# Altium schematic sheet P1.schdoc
size 297 x 209 mm; Symbol: Drawing-Symbol_A4; @Create Time: 13:52:45; @Update Time: 20:21:33; Border: 1; Width: 1170; Height: 825; Region Start: 1; X Region Count: 6; Y Region Count: 4; Blade Width: 10; Title Block Position: 3; Title Block: 1; @Board Name: ADC; Company: 嘉立创EDA; Version: V1.0; Page Size: A4; @Project Name: stm32f4; @Page Count: 1; @Update Date: 2025-11-17; @Create Date: 2025-11-02; @Schematic Name: Schematic2; @Page No: 1; @Page Name: P1; Device: Drawing-Symbol_A4
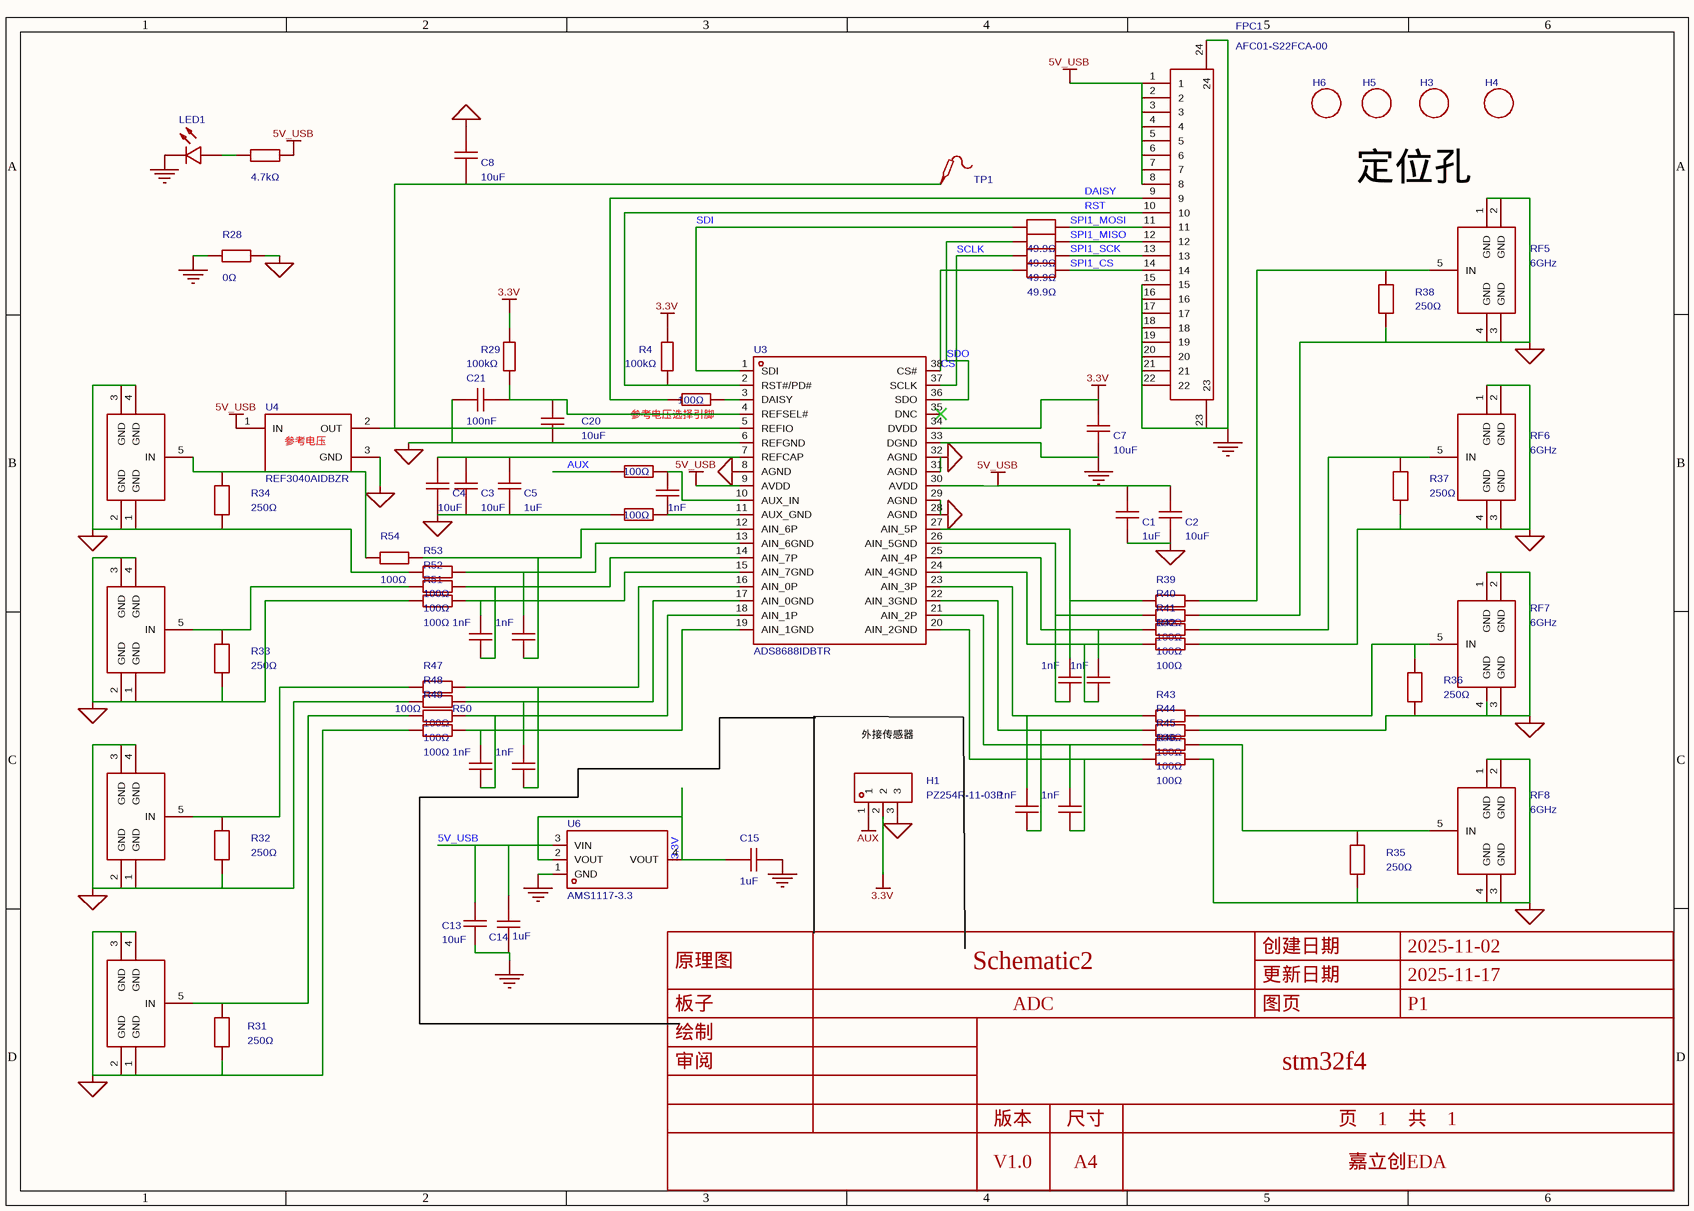
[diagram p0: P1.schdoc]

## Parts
C1  1uF  [C0603]
C2  10uF  [C0603]
C3  10uF  [C0603]
C4  10uF  [C0603]
C5  1uF  [C0603]
C6  1nF  [C0603]
C7  10uF  [C0603]
C8  10uF  [C0603]
C9  1nF  [C0603]
C10  1nF  [C0603]
C11  1nF  [C0603]
C12  1nF  [C0603]
C13  10uF  [C0603]
C14  1uF  [C0603]
C15  1uF  [C0603]
C16  1nF  [C0603]
C17  1nF  [C0603]
C18  1nF  [C0603]
C19  1nF  [C0603]
C20  10uF  [C0603]
C21  100nF  [C0402]
FPC1  AFC01-S22FCA-00  [FPC-SMD_P0.5-22P_FGS-XJ-H2.0]
H1  PZ254R-11-03P  [HDR-TH_3P-P2.54-H-M-W10.4]
H3  m3_3  [m3 125x300]  (value not drawn)
H4  m3_3  [m3 125x300]  (value not drawn)
H5  m3_3  [m3 125x300]  (value not drawn)
H6  m3_3  [m3 125x300]  (value not drawn)
LED1  19-217/R6C-AL1M2VY/3T  [LED0603-RD]  (value not drawn)
R1  100Ω  [R0603]
R3  100Ω  [R0603]
R4  100kΩ  [R0603]
R26  4.7kΩ  [R0402]
R28  0Ω  [R0603]
R29  100kΩ  [R0603]
R30  100Ω  [R0603]
R31  250Ω  [R1206]
R32  250Ω  [R1206]
R33  250Ω  [R1206]
R34  250Ω  [R1206]
R35  250Ω  [R1206]
R36  250Ω  [R1206]
R37  250Ω  [R1206]
R38  250Ω  [R1206]
R39  100Ω  [R0603]
R40  100Ω  [R0603]
R41  100Ω  [R0603]
R42  100Ω  [R0603]
R43  100Ω  [R0603]
R44  100Ω  [R0603]
R45  100Ω  [R0603]
R46  100Ω  [R0603]
R47  100Ω  [R0603]
R48  100Ω  [R0603]
R49  100Ω  [R0603]
R50  100Ω  [R0603]
R51  100Ω  [R0603]
R52  100Ω  [R0603]
R53  100Ω  [R0603]
R54  100Ω  [R0603]
R55  49.9Ω  [R0603]
R56  49.9Ω  [R0603]
R57  49.9Ω  [R0603]
R58  49.9Ω  [R0603]
RF1  6GHz  [ANT-TH_KH-SMA-K513-G]  (value not drawn)
RF2  6GHz  [ANT-TH_KH-SMA-K513-G]  (value not drawn)
RF3  6GHz  [ANT-TH_KH-SMA-K513-G]  (value not drawn)
RF4  6GHz  [ANT-TH_KH-SMA-K513-G]  (value not drawn)
RF5  6GHz  [ANT-TH_KH-SMA-K513-G]
RF6  6GHz  [ANT-TH_KH-SMA-K513-G]
RF7  6GHz  [ANT-TH_KH-SMA-K513-G]
RF8  6GHz  [ANT-TH_KH-SMA-K513-G]
TP1  (no value)  [Test-Point-0.5mm]
U3  ADS8688IDBTR  [TSSOP-38_L9.7-W4.4-P0.50-LS6.4-BL]
U4  REF3040AIDBZR  [SOT-23-3_L2.9-W1.6-P1.90-LS2.8-BR]
U6  AMS1117-3.3  [SOT-223-3_L6.5-W3.4-P2.30-LS7.0-BR]

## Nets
3.3V: C7.1 C15.1 H1.2 R4.2 R29.2 U3.34(DVDD) U6.2(VOUT) U6.4(VOUT)
5V_USB: C1.1 C2.1 C13.2 C14.2 FPC1.1 FPC1.2 FPC1.3 FPC1.4 FPC1.5 FPC1.6 FPC1.7 FPC1.8 R26.2 U3.9(AVDD) U3.30(AVDD) U4.1(IN) U6.3(VIN)
AGND: C1.2 C2.2 C3.1 C4.1 C5.2 C8.1 C20.2 C21.2 H1.3 R1.1 R28.2 R31.1 R32.1 R33.1 R34.1 R35.1 R36.1 R37.1 R38.2 R40.2 R42.2 R44.2 R46.2 R48.1 R50.1 R51.1 R53.1 RF1.1(GND) RF1.2(GND) RF1.3(GND) RF1.4(GND) RF2.1(GND) RF2.2(GND) RF2.3(GND) RF2.4(GND) RF3.1(GND) RF3.2(GND) RF3.3(GND) RF3.4(GND) RF4.1(GND) RF4.2(GND) RF4.3(GND) RF4.4(GND) RF5.1(GND) RF5.2(GND) RF5.3(GND) RF5.4(GND) RF6.1(GND) RF6.2(GND) RF6.3(GND) RF6.4(GND) RF7.1(GND) RF7.2(GND) RF7.3(GND) RF7.4(GND) RF8.1(GND) RF8.2(GND) RF8.3(GND) RF8.4(GND) U3.6(REFGND) U3.8(AGND) U3.28(AGND) U3.29(AGND) U3.31(AGND) U3.32(AGND) U4.3(GND)
AUX: H1.1 R30.1
GND: C7.2 C13.1 C14.1 C15.2 FPC1.15 FPC1.16 FPC1.17 FPC1.18 FPC1.19 FPC1.20 FPC1.21 FPC1.22 FPC1.23 FPC1.24 LED1.1(C) R28.1 U3.33(DGND) U6.1(GND)
CS: R58.1 U3.38(CS#)
DAISY: FPC1.9 R3.1
RST: FPC1.10 R4.1 U3.2(RST#/PD#)
SCLK: R57.1 U3.37(SCLK)
SDI: R55.1 U3.1(SDI)
SDO: R56.1 U3.36(SDO)
SPI1_CS: FPC1.14 R58.2
SPI1_MISO: FPC1.12 R56.2
SPI1_MOSI: FPC1.11 R55.2
SPI1_SCK: FPC1.13 R57.2
NetC3_2: C3.2 C4.2 C5.1 U3.7(REFCAP)
NetC6_1: C6.1 R1.2 U3.11(AUX_GND)
NetC6_2: C6.2 R30.2 U3.10(AUX_IN)
NetC8_2: C8.2 TP1.1 U3.5(REFIO) U4.2(OUT)
NetC9_1: C9.1 R51.2 U3.15(AIN_7GND)
NetC9_2: C9.2 R52.2 U3.14(AIN_7P)
NetC10_1: C10.1 R53.2 U3.13(AIN_6GND)
NetC10_2: C10.2 R54.2 U3.12(AIN_6P)
NetC11_1: C11.1 R50.2 U3.19(AIN_1GND)
NetC11_2: C11.2 R49.2 U3.18(AIN_1P)
NetC12_1: C12.1 R48.2 U3.17(AIN_0GND)
NetC12_2: C12.2 R47.2 U3.16(AIN_0P)
NetC16_1: C16.1 R43.1 U3.23(AIN_3P)
NetC16_2: C16.2 R44.1 U3.22(AIN_3GND)
NetC17_1: C17.1 R45.1 U3.21(AIN_2P)
NetC17_2: C17.2 R46.1 U3.20(AIN_2GND)
NetC18_1: C18.1 R41.1 U3.25(AIN_4P)
NetC18_2: C18.2 R42.1 U3.24(AIN_4GND)
NetC19_1: C19.1 R39.1 U3.27(AIN_5P)
NetC19_2: C19.2 R40.1 U3.26(AIN_5GND)
NetC20_1: C20.1 C21.1 R29.1 U3.4(REFSEL#)
NetLED1_2: LED1.2(A) R26.1
NetR3_2: R3.2 U3.3(DAISY)
NetR31_2: R31.2 R49.1 RF4.5(IN)
NetR32_2: R32.2 R47.1 RF3.5(IN)
NetR33_2: R33.2 R52.1 RF2.5(IN)
NetR34_2: R34.2 R54.1 RF1.5(IN)
NetR35_2: R35.2 R45.2 RF8.5(IN)
NetR36_2: R36.2 R43.2 RF7.5(IN)
NetR37_2: R37.2 R41.2 RF6.5(IN)
NetR38_1: R38.1 R39.2 RF5.5(IN)

Not connected (* = marked no-connect by the designer): U3 35(DNC)*

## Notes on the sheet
- 定位孔
- (near U4) 参考电压
- (near R3) 参考电压选择引脚
- 外接传感器

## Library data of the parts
C1 C5 C14 C15 = CL10A105KB8NNNC: 容值:1uF;精度:±10%;额定电压:50V;温度系数:X5R;; Manufacturer: SAMSUNG(三星); AddInBom: yes; ModelId: ac125912035d415993ca9572d50418b1; ModelName: C0603_L1.6-W0.8-H0.8; ModelTransform: 62.992,31.496,0,0,0,0,0,0,0; Tolerance: ±10%; Voltage Rating: 50V; Temperature Coefficient: X5R
C2-C4 C7 C8 = 0603X106M250NT: 容值:10uF;精度:±20%;额定电压:25V;温度系数:X5R;; Manufacturer: FH(风华); AddInBom: yes; ModelId: ac125912035d415993ca9572d50418b1; ModelName: C0603_L1.6-W0.8-H0.8; ModelTransform: 62.992,31.496,0,0,0,0,0,0,0; Tolerance: ±20%; Voltage Rating: 25V; Temperature Coefficient: X5R
C6 C9-C12 C16-C19 = CL10B102KB8NNNC: 容值:1nF;精度:±10%;额定电压:50V;温度系数:X7R;; Manufacturer: SAMSUNG(三星); AddInBom: yes; ModelId: ac125912035d415993ca9572d50418b1; ModelName: C0603_L1.6-W0.8-H0.8; ModelTransform: 62.992,31.496,0,0,0,0,0,0,0; Tolerance: ±10%; Voltage Rating: 50V; Temperature Coefficient: X7R
C13 C20 = 0603X106K100NT: 容值:10uF;精度:±10%;额定电压:10V;材质(温度系数):X5R;; Manufacturer: FH(风华); AddInBom: yes; ModelId: ac125912035d415993ca9572d50418b1; ModelName: C0603_L1.6-W0.8-H0.8; ModelTransform: 62.992,31.496,0,0,0,0,0,0,0; Tolerance: ±10%; Voltage Rated: 10V; Temperature Coefficient: X5R
C21 = CC0402KRX7R7BB104: 容值:100nF;精度:±10%;额定电压:16V;材质(温度系数):X7R;; Manufacturer: YAGEO(国巨); AddInBom: yes; ModelId: 36a51122f27c49738f86b3bfa98863e0; ModelName: C0402_L1.0-W0.5-H0.5; ModelTransform: 39.37,19.685,0,0,0,0,0,0,0; Tolerance: ±10%; Voltage Rated: 16V; Temperature Coefficient: X7R
FPC1 = AFC01-S22FCA-00: 锁定特性:翻盖式;触点类型:下接;触点数量:22P;间距:0.5mm;安装类型:卧贴;; Manufacturer: JS(钜硕电子); AddInBom: yes; ModelId: 12d9165dec84425d968f174b1be8289a; ModelTransform: 610.235,240.157,0,0,0,0,0,57.008,0; Locking Feature: 翻盖式; Number of Contacts: 22P; Pitch: 0.5mm; FFC, FCB Thickness: 0.3mm
H1 = PZ254R-11-03P: 插针结构:1x3P;间距:2.54mm;行距:-;圆针/方针:方针;安装方式:弯插;排数:单排;总PIN位数:3P;额定电流:-;额定电压:-;配合针长度:6mm;塑高:2.5mm;触头材质:黄铜;触头镀层:-;工作温度:-40℃~+105℃;颜色:黑色;; Manufacturer: XFCN(兴飞); AddInBom: yes; ModelId: 3631fb14048f41fcbbc4081ca5f7f71f; ModelName: HDR-TH_3P-P2.54-M-WI-1X3P; ModelTransform: 299.9994,409.448,0,0,0,0,0,-190.945,-118.11; Pin Structure: 1x3P; Pitch: 2.54mm; Circluar Pins/Square Pins: 方针
H3-H6 = m3_3: Symbol: m3; AddInBom: yes
LED1 = 19-217/R6C-AL1M2VY/3T: 发光颜色:红色;正向压降(Vf):1.95V;功率:60mW;正向电流:5mA;波长:617.5nm;二极管配置:-;透镜颜色:无色透明透镜;色温:-;发光角度:120°;载带方式:-;工作温度:-40℃~+85℃;; Manufacturer: EVERLIGHT(亿光); AddInBom: yes; ModelId: 1f0d29a91be547639d425604e9b96ebb; ModelTransform: 63.7794,32.283,0,0,0,0,0,0,0; Illumination Color: 红色; Voltage - Forward(Vf): 1.95V; Power(Watts): 60mW; Forward Current: 5mA; Peak Wavelength: 632nm; Lens Color: 无色透明透镜; Viewing Angle: 120°
R1 R3 R30 R39-R54 = 0603WAF1000T5E: 电阻类型:厚膜电阻;阻值:100Ω;精度:±1%;功率:100mW;最大工作电压:75V;温度系数:±200ppm/℃;; Manufacturer: UNI-ROYAL(厚声); AddInBom: yes; ModelId: fc143cca1e79419f9cd78b61e9279f08; ModelTransform: 31.8897,63.7794,0,90,0,0,0,0,0; Tolerance: ±1%; Power(Watts): 100mW; Overload Voltage (Max): 75V
R4 R29 = 0603WAF1003T5E: 电阻类型:厚膜电阻;阻值:100kΩ;精度:±1%;功率:100mW;工作电压:75V;温度系数:±100ppm/℃;; Manufacturer: UNI-ROYAL(厚声); AddInBom: yes; ModelId: fc143cca1e79419f9cd78b61e9279f08; ModelTransform: 31.8897,63.7794,0,90,0,0,0,0,0; Tolerance: ±1%; Power(Watts): 100mW; Voltage-Supply(Max): 75V
R26 = 0402WGF4701TCE: 电阻类型:厚膜电阻;阻值:4.7kΩ;精度:±1%;功率:62.5mW;工作电压:50V;温度系数:±100ppm/℃;; Manufacturer: UNI-ROYAL(厚声); AddInBom: yes; ModelId: 98c88bc2b9094f218f3a3e30a7012738; ModelName: R0402_L1.0-W0.5-H0.4; ModelTransform: 39.37,19.685,0,0,0,0,0,0,0; Tolerance: ±1%; Power(Watts): 62.5mW; Voltage-Supply(Max): 50V
R28 = 0603WAF0000T5E: 电阻类型:厚膜电阻;阻值:0Ω;精度:±1%;功率:100mW;工作电压:75V;温度系数:-;; Manufacturer: UNI-ROYAL(厚声); AddInBom: yes; ModelId: fc143cca1e79419f9cd78b61e9279f08; ModelTransform: 31.8897,63.7794,0,90,0,0,0,0,0; Tolerance: ±1%; Power(Watts): 100mW; Voltage-Supply(Max): 75V
R31-R38 = PTFR1206B250RP9: 电阻类型:薄膜电阻;阻值:250Ω;精度:±0.1%;功率:250mW;工作电压:200V;温度系数:±25ppm/℃;; Manufacturer: RESI(开步睿思); AddInBom: yes; ModelId: 89a1f13db2384da588040e0b3c55bf66; ModelName: R1206_L3.2-W1.6-H0.6; ModelTransform: 125.984,62.992,0,0,0,0,0,0,0; Tolerance: ±0.1%; Power(Watts): 250mW; Voltage-Supply(Max): 200V
R55-R58 = FRC0603F49R9TS: 电阻类型:厚膜电阻;阻值:49.9Ω;精度:±1%;功率:100mW;工作电压:75V;温度系数:±100ppm/℃;; Manufacturer: FOJAN(富捷); AddInBom: yes; ModelId: fc143cca1e79419f9cd78b61e9279f08; ModelTransform: 31.8897,63.7794,0,90,0,0,0,0,0; Tolerance: ±1%; Power(Watts): 100mW; Voltage-Supply(Max): 75V
RF1-RF8 = KH-SMA-K513-G: 连接器类型:板端;接口类型:内孔;端口数量:1;接口直径:-;接口长度/高度:-;频率:6GHz;射频系列:SMA;阻抗:50Ω;样式:弯头;工作温度:-55℃~+155℃;; Manufacturer: kinghelm(金航标); AddInBom: yes; ModelId: d7d2010d82e6431cb2146b4719b2209b; ModelName: ANT-TH_L14.8-W6.4-H10.0; ModelTransform: 582.676,249.9995,0,0,0,0,-169.291,0,-137.795; Connector Type: 板端; Interface: 内孔; Number of Ports: 1; RF Series: SMA; Impedance: 50Ω; Style: 弯头
TP1 = Test-Point: Test Point 测试点; AddInBom: yes
U3 = ADS8688IDBTR: 分辨率:16位;采样率:500kHz;工作电压:5V;接口类型:SPI;; Manufacturer: TI(德州仪器); AddInBom: yes; ModelId: 6fc8ae0b31e54feeb05b0ccf963847a5; ModelName: TSSOP-38_L9.7-W4.4-H1.0-LS6.4-P0.50; ModelTransform: 381.889,251.968,0,0,0,0,0,0,0; Resolution(Bits): 16位; Sampling Rate: 500kHz; number of channels: 8; Voltage - Supply: 5V; Interface: SPI; differential input: 否; Integral non - linearity: 0.75LSB; Signal-to-Noise Ratio: 92dB; Clock Frequency: 17MHz; Voltage Reference: 内置; Voltage Reference Drift: 6ppm/℃; ADC architecture: SAR; Full-Scale Range(FSR): 10.24V
U4 = REF3040AIDBZR: REF3040 采用 SOT23-3 封装的 4.096V 输出 50ppm/℃ 漂移 50uA 静态电流的（带隙）电压参考系列; Manufacturer: TI(德州仪器); AddInBom: yes; ModelId: 89cb27a44ab2466697082bb9fd73a7d0; ModelName: SOT-23-3L_L2.9-W1.6-H1.1-LS2.8-P0.95; ModelTransform: 110.236,114.173,0,180,0,0,-0.005,0.0005,0
U6 = AMS1117-3.3_C6186: 输出类型:固定;工作电压:16V;输出电压:3.3V;输出电流:1A;电源纹波抑制比(PSRR):72dB@(120Hz);输出极性:正极;; Manufacturer: AMS; AddInBom: yes; ModelId: 925194bf9823436183a3e0b978a8d076; ModelName: SOT-223-4P_L6.5-W3.5-H1.6-LS7.0-P2.30; ModelTransform: 279.89794,255.905,0,180,0,0,-3.9385,-0.0005,0; Output Type: 固定; Voltage - Supply: 16V; Output Voltage: 3.3V; Output Current: 1A; Voltage Dropout: 1.1V@(800mA); standby current: 5mA; Noise: 0.003%Vout; Output Configuration: 正极; Number of Outputs: 1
